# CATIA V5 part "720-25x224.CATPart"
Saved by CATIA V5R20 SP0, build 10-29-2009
Part number: 720-25x224
Definition: NONE
Nomenclature: 720-25x224
Source: Unknown
Description: 720-25x224
Bounding box of the stored display mesh (mm): x 0 to 224, y -12.5 to 12.5, z -12.5 to 12.5
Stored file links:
  C:\Users\Utente\Desktop\IO LAVORO\3D X SITO CF\X SITO\720\720-25x224.CATPart
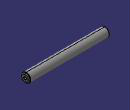
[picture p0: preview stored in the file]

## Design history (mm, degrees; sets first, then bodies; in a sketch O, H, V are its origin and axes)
Body1 "720-25x224" (main body)
  Solid1: solid without history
